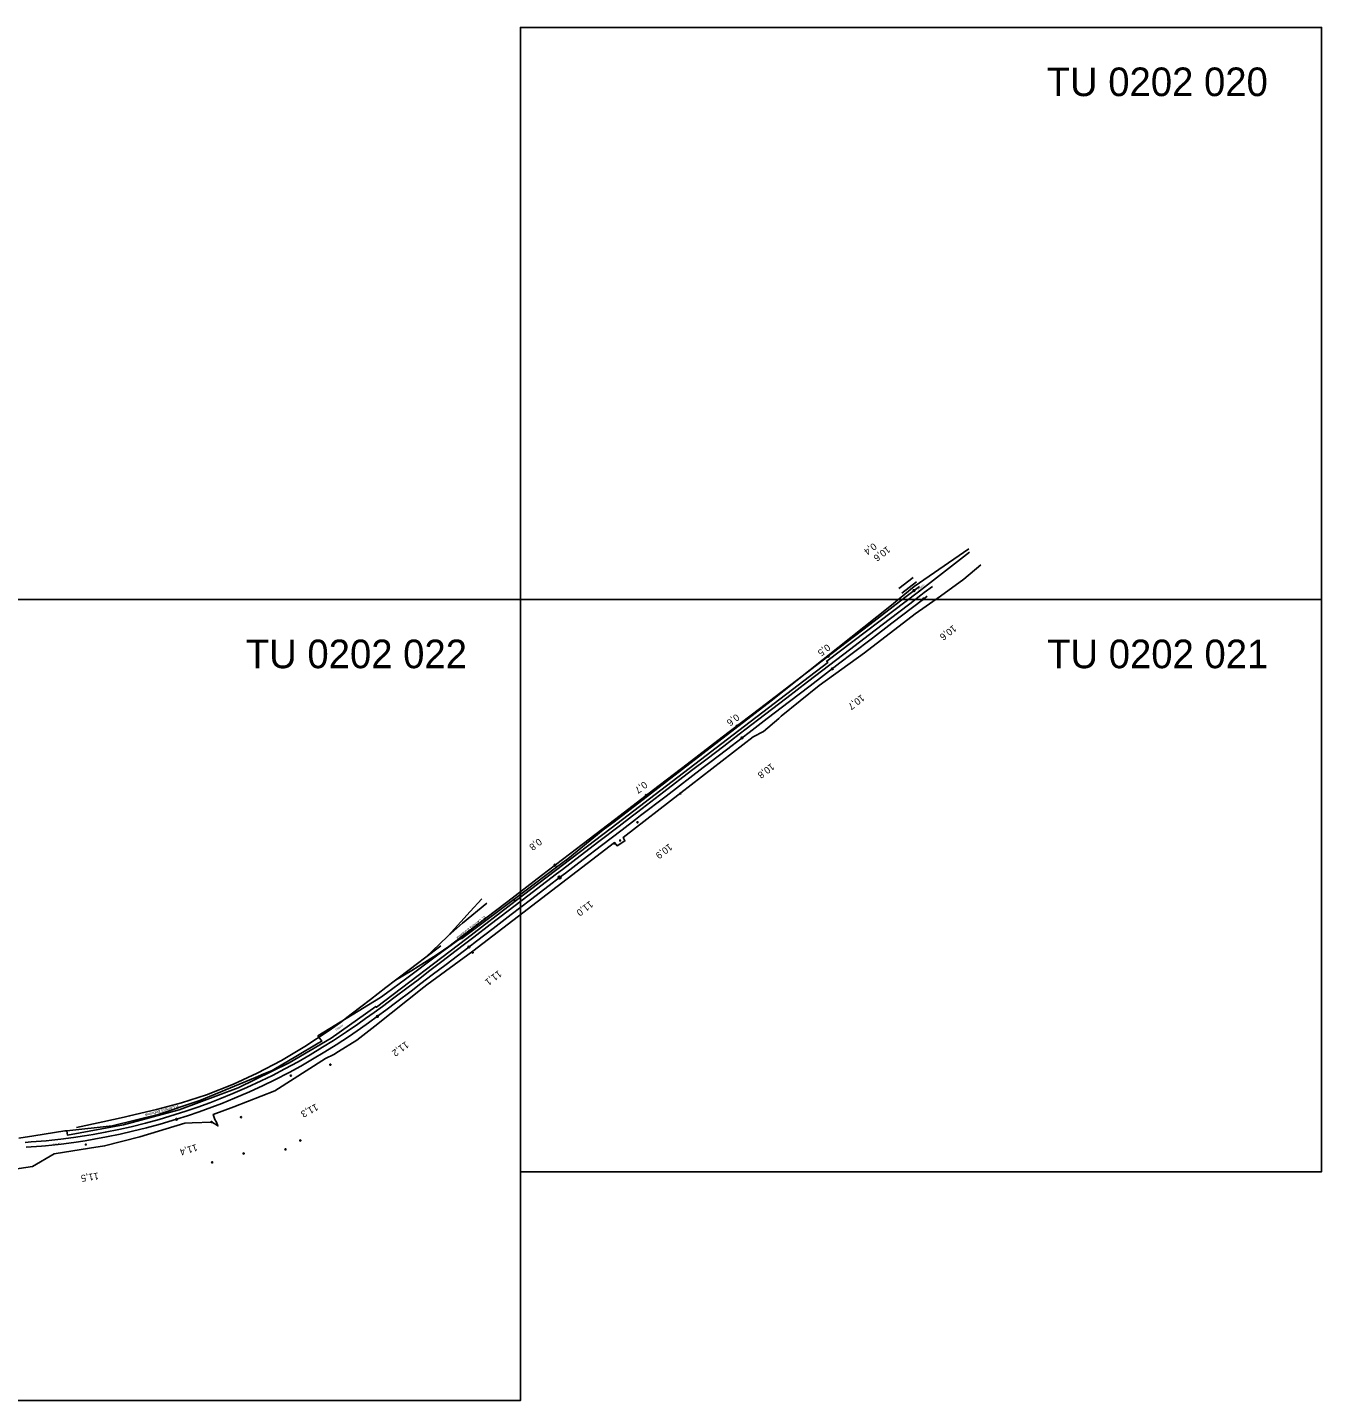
# Model space of a CAD drawing. Extents: x -768800 to -748700, y -1061452 to -1051366.
# Drawn here: x -749831 to -748700, y -1054900 to -1053700 of the extents above; entities that cross this region are included whole.
import ezdxf

# ---------------------------------------------------------------- set-up
doc = ezdxf.new("R2010")
doc.units = 0
for name, color, linetype in [('Vrstva 1', 7, 'Continuous'), ('Vrstva 2', 7, 'Continuous'), ('Vrstva 53', 7, 'Continuous'), ('Vrstva 55', 7, 'Continuous'), ('Vrstva 57', 7, 'Continuous'), ('Vrstva 7', 7, 'Continuous')]:
    doc.layers.add(name, color=color, linetype=linetype)

msp = doc.modelspace()

# ---------------------------------------------------------------- linework, layer by layer
at = {"layer": 'Vrstva 1'}
for p, q in [((-749047.1, -1054193.9), (-749050.1, -1054196.2)), ((-749044.5, -1054197.1), (-749047.7, -1054199.5)), ((-749463.3, -1054493.8), (-749450.7, -1054482.9)), ((-749482.8, -1054512.6), (-749469.6, -1054502.5)), ((-749509.2, -1054532.7), (-749494.9, -1054524.2))]:
    msp.add_line(p, q, dxfattribs=at)
for points in [[(-749400, -1054200), (-749400, -1053700), (-748700, -1053700), (-748700, -1054200), (-749400, -1054200)], [(-749056.9, -1054180.8), (-749069.5, -1054190.4)], [(-749053.9, -1054184.5), (-749066.8, -1054194.3)], [(-749900, -1054900), (-749900, -1054200), (-749400, -1054200), (-749400, -1054900), (-749900, -1054900)], [(-749050.1, -1054196.2), (-749059.8, -1054203.6), (-749077.8, -1054217.4), (-749095, -1054230.6), (-749112.5, -1054244), (-749123.4, -1054252.3), (-749149.1, -1054272), (-749167.3, -1054286), (-749186.7, -1054300.8), (-749202.7, -1054313), (-749208.8, -1054317.7), (-749222.2, -1054328), (-749236.8, -1054339.2), (-749250.4, -1054349.5), (-749274.6, -1054368.1), (-749297.4, -1054385.5), (-749302, -1054389), (-749313.6, -1054397.9), (-749331.4, -1054411.5), (-749347.8, -1054424.1), (-749363.2, -1054435.8), (-749368.5, -1054439.8), (-749377.2, -1054446.5), (-749393.4, -1054458.9), (-749410.6, -1054472), (-749426.4, -1054484.1), (-749440.7, -1054495), (-749447.8, -1054500.4), (-749457.3, -1054507.6), (-749467.6, -1054515.5), (-749480.3, -1054525.1), (-749489.5, -1054532.2), (-749498.2, -1054538.8), (-749510.5, -1054548.1), (-749520.6, -1054555.6), (-749527.8, -1054560.8), (-749535.3, -1054566.2), (-749542.2, -1054571.1), (-749551.9, -1054577.7), (-749563.5, -1054585.3), (-749573, -1054591.3), (-749583.8, -1054597.9), (-749594.3, -1054603.9), (-749605.8, -1054610.2), (-749616.7, -1054615.8), (-749626.6, -1054620.7), (-749639.1, -1054626.5), (-749651.4, -1054631.8), (-749662.6, -1054636.4), (-749671.3, -1054639.7), (-749681.9, -1054643.6), (-749692.3, -1054647.1), (-749701.7, -1054650.1), (-749715.8, -1054654.3), (-749727.6, -1054657.5), (-749740.3, -1054660.7), (-749751, -1054663.1), (-749762.8, -1054665.5), (-749773.3, -1054667.4), (-749781, -1054668.7), (-749790.4, -1054670.1), (-749801.6, -1054671.5), (-749809.6, -1054672.4), (-749814.3, -1054672.9), (-749827.5, -1054674), (-749832.7, -1054674.4)], [(-749047.7, -1054199.5), (-749057.4, -1054206.9), (-749075.5, -1054220.7), (-749092.4, -1054233.7), (-749110.1, -1054247.2), (-749120.9, -1054255.4), (-749146.8, -1054275.3), (-749164.9, -1054289.2), (-749184.3, -1054304), (-749200.1, -1054316.1), (-749206.4, -1054320.9), (-749219.9, -1054331.2), (-749234.5, -1054342.5), (-749240.3, -1054346.9), (-749272.7, -1054371.7), (-749295, -1054388.8), (-749299.5, -1054392.2), (-749311.2, -1054401.1), (-749329.1, -1054414.8), (-749345.3, -1054427.2), (-749360.7, -1054439), (-749365.9, -1054443), (-749374.9, -1054449.9), (-749391.1, -1054462.3), (-749408.2, -1054475.3), (-749423.9, -1054487.4), (-749438.4, -1054498.4), (-749445.2, -1054503.7), (-749455.1, -1054511.3), (-749465, -1054518.8), (-749477.1, -1054528.1), (-749486.9, -1054535.6), (-749495.6, -1054542.2), (-749507.9, -1054551.6), (-749517.6, -1054558.8), (-749524.9, -1054564.2), (-749532.8, -1054569.9), (-749539.8, -1054574.9), (-749549.5, -1054581.5), (-749561, -1054589.1), (-749570.8, -1054595.3), (-749581.6, -1054601.8), (-749591.9, -1054607.7), (-749602.1, -1054613.2), (-749614.5, -1054619.6), (-749624.8, -1054624.6), (-749636.9, -1054630.2), (-749649.8, -1054635.8), (-749660.9, -1054640.3), (-749669.8, -1054643.7), (-749680.8, -1054647.7), (-749690.9, -1054651.1), (-749700.5, -1054654.2), (-749714.7, -1054658.4), (-749726.9, -1054661.7), (-749739.1, -1054664.7), (-749749.9, -1054667.2), (-749761.8, -1054669.6), (-749772.7, -1054671.6), (-749780.4, -1054672.9), (-749790.3, -1054674.4), (-749801.3, -1054675.8), (-749809.4, -1054676.7), (-749814.9, -1054677.3), (-749818.6, -1054677.6), (-749831.8, -1054678.6)], [(-749064, -1054198.2), (-749094.8, -1054221.7), (-749127.5, -1054246.8), (-749158.9, -1054270.8), (-749191.1, -1054295.4), (-749223.6, -1054320.3), (-749254.4, -1054343.8), (-749283.6, -1054366.2), (-749317.8, -1054392.4), (-749351, -1054417.8), (-749381.6, -1054441.1), (-749411.1, -1054463.8)], [(-749400, -1054700), (-749400, -1054200), (-748700, -1054200), (-748700, -1054700), (-749400, -1054700)], [(-749051.4, -1054188.5), (-749064, -1054198.2)], [(-749040, -1054188.5), (-749047.1, -1054193.9)], [(-749411.1, -1054463.8), (-749422.9, -1054472.8), (-749444, -1054488.9), (-749462.7, -1054503.1), (-749472.8, -1054510.3), (-749494.9, -1054524.2)], [(-749491.2, -1054519), (-749482.8, -1054512.6), (-749470.8, -1054501.1), (-749463.3, -1054493.8), (-749452, -1054481.6), (-749443.8, -1054472.7), (-749433.7, -1054461.6)], [(-749450.7, -1054482.9), (-749429.5, -1054465.4)], [(-749517.5, -1054539.1), (-749509.2, -1054532.7), (-749496, -1054522.7)], [(-749496, -1054522.7), (-749491.2, -1054519)], [(-749517.5, -1054539.1), (-749531, -1054549.4), (-749547.8, -1054562.3), (-749557.3, -1054569.5), (-749567.1, -1054576.6), (-749588.5, -1054590.6), (-749608.8, -1054602.7), (-749630, -1054613.9), (-749650.7, -1054623.4), (-749674.2, -1054632.7), (-749696.1, -1054639.8), (-749718, -1054645.7), (-749741.5, -1054651.2), (-749746.3, -1054652.3), (-749764.8, -1054656.4), (-749788, -1054661.5)]]:
    msp.add_lwpolyline(points, dxfattribs=at)
at = {"layer": 'Vrstva 53'}
for p, q in [((-749260.1, -1054369.5), (-749260.2, -1054369.6)), ((-749260.2, -1054369.5), (-749260.1, -1054369.5)), ((-749317.8, -1054413), (-749317.9, -1054413.1)), ((-749312.8, -1054410.5), (-749312.9, -1054410.5)), ((-749441.9, -1054508.5), (-749441.8, -1054508.5)), ((-749566.1, -1054606.5), (-749566, -1054606.5)), ((-749644.2, -1054652.3), (-749644.1, -1054652.3)), ((-749670, -1054656.6), (-749669.9, -1054656.6)), ((-749592.4, -1054672.8), (-749592.3, -1054672.8)), ((-749669.5, -1054691.8), (-749669.4, -1054691.8)), ((-749641.8, -1054684.1), (-749641.7, -1054684.1)), ((-749605.3, -1054680.4), (-749605.2, -1054680.4))]:
    msp.add_line(p, q, dxfattribs=at)
for points in [[(-749838.3, -1054670.7), (-749825.1, -1054668.6), (-749798, -1054664.4), (-749796.4, -1054664.2), (-749756.9, -1054659.9), (-749716.5, -1054649.9), (-749680.2, -1054637.9), (-749631.6, -1054617.7), (-749624.2, -1054614.6), (-749617, -1054611.6), (-749615.5, -1054610.7), (-749596.2, -1054599.3), (-749576.7, -1054587.7), (-749573.5, -1054585.8), (-749577, -1054581.3), (-749522.2, -1054547.9), (-749517, -1054544), (-749500.5, -1054531.7), (-749472.1, -1054510.6), (-749454.2, -1054497.3), (-749452.4, -1054496.6), (-749451.2, -1054496.2), (-749405.7, -1054462), (-749368.5, -1054434), (-749358.6, -1054426.6), (-749327.7, -1054401.3), (-749318.2, -1054394.1), (-749180.8, -1054288.5), (-749077.1, -1054206.1), (-749056, -1054188.7), (-749008.3, -1054155.6)], [(-748997.7, -1054169.5), (-749012.5, -1054182.1), (-749032.9, -1054197.1), (-749055.1, -1054212.6), (-749099.5, -1054246.6), (-749138.9, -1054275.1), (-749172.2, -1054302), (-749174.2, -1054303.8), (-749187.7, -1054315.4), (-749196.6, -1054320), (-749259.8, -1054369), (-749310.3, -1054408), (-749308.7, -1054410.9), (-749315.6, -1054415.2), (-749317.8, -1054412.4), (-749341.7, -1054430.8), (-749441.7, -1054507.2), (-749481.8, -1054536.8), (-749484.3, -1054538.6), (-749527.1, -1054572.9), (-749543.1, -1054585), (-749558.9, -1054594.9), (-749563.1, -1054597.5), (-749570.4, -1054601.2), (-749614.7, -1054629.4), (-749650.4, -1054643.2), (-749668.5, -1054649.9), (-749667.1, -1054654.5), (-749665.5, -1054656.7), (-749664.3, -1054660), (-749667, -1054658.3), (-749669.8, -1054656.6), (-749686.8, -1054657.2), (-749693.3, -1054657.5), (-749732.5, -1054669.6), (-749763.4, -1054677.5), (-749776.7, -1054679.4), (-749807.4, -1054684.4), (-749826.3, -1054695.4), (-749853.4, -1054699.5)]]:
    msp.add_lwpolyline(points, dxfattribs=at)
for centre in [(-749260.1, -1054369.5), (-749260.1, -1054369.5), (-749317.9, -1054413), (-749312.9, -1054410.5), (-749441.8, -1054508.5), (-749566.1, -1054606.5), (-749644.2, -1054652.3), (-749669.9, -1054656.6), (-749605.3, -1054680.4), (-749592.3, -1054672.8), (-749669.4, -1054691.8), (-749641.8, -1054684.1)]:
    msp.add_circle(centre, 0.499, dxfattribs=at)
at = {"layer": 'Vrstva 55'}
for points in [[(-749404.6, -1054463.6), (-749320.8, -1054399.7), (-749204.2, -1054310.6), (-749131.5, -1054254.9), (-749132.3, -1054253.8), (-749052.2, -1054193.1), (-749007.5, -1054158.6)], [(-749796.4, -1054664.2), (-749795.8, -1054668), (-749746.9, -1054659), (-749698.3, -1054645.9), (-749646.8, -1054626.6), (-749602, -1054604.9), (-749565.5, -1054583.3), (-749526.4, -1054555.5), (-749525.8, -1054556.3), (-749446.9, -1054496.2), (-749404.6, -1054463.6), (-749405.7, -1054462)]]:
    msp.add_lwpolyline(points, dxfattribs=at)
at = {"layer": 'Vrstva 7'}
for p, q in [((-749297.7, -1054394.6), (-749297.8, -1054394.7)), ((-749600.6, -1054616), (-749600.6, -1054616.1)), ((-749779.8, -1054676.3), (-749779.9, -1054676.3))]:
    msp.add_line(p, q, dxfattribs=at)
for centre, radius in [((-749056.2, -1054192.1), 0.75), ((-749047.7, -1054199.4), 0.75), ((-749131.1, -1054249.6), 0.75), ((-749127.5, -1054260.5), 0.75), ((-749210.8, -1054310.5), 0.75), ((-749206.4, -1054320.9), 0.75), ((-749290.1, -1054371.2), 0.75), ((-749297.7, -1054394.7), 0.5), ((-749369.8, -1054432.1), 0.75), ((-749365.8, -1054442.9), 1.25), ((-749365.8, -1054442.9), 0.752), ((-749445.1, -1054503.6), 0.75), ((-749525, -1054564.3), 0.75), ((-749600.6, -1054616.1), 0.5), ((-749700.5, -1054654.2), 0.75), ((-749779.8, -1054676.3), 0.5)]:
    msp.add_circle(centre, radius, dxfattribs=at)

# ---------------------------------------------------------------- texts
at = {"layer": 'Vrstva 1'}
for s, rotation, p in [('vl. Cement Bohemia', 217.4227, (-749431.4, -1054476.2)), ('vl.Cement Bohemia', 195.1067, (-749699.1, -1054641.7))]:
    msp.add_text(s, height=2.5, rotation=rotation, dxfattribs=at).set_placement(p)
at = {"layer": 'Vrstva 2'}
for s, p in [('TU 0202 020', (-748940.2, -1053760)), ('TU 0202 022', (-749640, -1054260)), ('TU 0202 021', (-748939.8, -1054260))]:
    msp.add_text(s, height=25, dxfattribs=at).set_placement(p)
at = {"layer": 'Vrstva 57'}
for s, rotation, p in [('1110/33', 221.2432, (-749047.3, -1054186.1)), ('1110/26', 212.4169, (-749555.4, -1054571.4)), ('2647/1', 188.1354, (-749802.1, -1054674.7))]:
    msp.add_text(s, height=1.5, rotation=rotation, dxfattribs=at).set_placement(p)
at = {"layer": 'Vrstva 7'}
for s, rotation, p in [('0,4', 217.3003, (-749091.6, -1054150.1)), ('10,6', 217.5013, (-749079.7, -1054152.9)), ('10,6', 217.4139, (-749021.8, -1054221.9)), ('0,5', 217.3868, (-749132, -1054238.5)), ('10,7', 217.4107, (-749102.1, -1054282.6)), ('0,6', 217.4421, (-749211.5, -1054299.5)), ('10,8', 217.4185, (-749180.9, -1054342.7)), ('0,7', 217.4369, (-749291.9, -1054358.5)), ('0,8', 217.4121, (-749384.1, -1054408.3)), ('10,9', 217.4343, (-749270.1, -1054412.9)), ('11,0', 217.4466, (-749339.3, -1054462.9)), ('11,1', 217.4386, (-749419.2, -1054523.6)), ('11,2', 216.4387, (-749500.3, -1054585.7)), ('11,3', 208.6416, (-749578.8, -1054640.3)), ('11,4', 197.7946, (-749683.4, -1054675.7)), ('11,5', 188.5029, (-749769, -1054700.7))]:
    msp.add_text(s, height=6, rotation=rotation, dxfattribs=at).set_placement(p)

doc.saveas('drawing.dxf')
